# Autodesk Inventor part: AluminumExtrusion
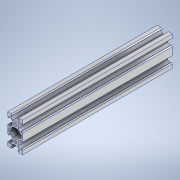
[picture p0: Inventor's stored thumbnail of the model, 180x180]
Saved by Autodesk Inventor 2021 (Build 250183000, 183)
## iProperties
Created: 2026-10
Part Number: AluminumExtrusion
Material: Aluminum 6061
Document SubType Name: Modeling
Designer: hp
Density: 2.7 g/cm^3
Appearance: Aluminum - Flat
Author: hp
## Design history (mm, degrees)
sketch "Sketch1"
  geometry: L1 (-10, -10)-(10, 10); L2 (2.839, -3.9)-(-2.839, -3.9); L3 (-3.9, -2.839)-(-3.9, 2.839); L4 (-2.839, 3.9)-(2.839, 3.9); L5 (3.9, 2.839)-(3.9, -2.839); L6 (3.9, -3.9)-(-3.9, 3.9); L7 (-3.9, -3.9)-(3.9, 3.9); L8 (-5.5, -8.28)-(-5.5, -6.561); L9 (-8.28, -5.5)-(-6.561, -5.5); L10 (-3.9, -2.839)-(-6.561, -5.5); L11 (-2.839, -3.9)-(-5.5, -6.561); L12 (0, -10)-(0, 10); L13 (5.5, -8.28)-(5.5, -6.561); L14 (2.839, -3.9)-(5.5, -6.561); L15 (3.9, -2.839)-(6.561, -5.5); L16 (-3.552, -8.707)-(-4.845, -10); L17 (-3.125, -8.28)-(-0.693, -8.28); L18 (3.552, -8.707)-(4.845, -10); L19 (-5.5, -8.28)-(-3.729, -8.28); L20 (3.729, -8.28)-(5.5, -8.28); L21 (10, -10)-(4.845, -10); L22 (-4.845, -10)-(-10, -10); L23 (-8.707, -3.552)-(-10, -4.845); L24 (-8.28, -5.5)-(-8.28, -3.729); L25 (-10, -4.845)-(-10, -10); L26 (8.707, -3.552)-(10, -4.845); L27 (8.28, -3.729)-(8.28, -5.5); L28 (8.28, -5.5)-(6.561, -5.5); L29 (10, -10)-(10, -4.845); L30 (-5.5, -8.28)-(-3.729, -8.28); L31 (-3.552, -8.707)-(-4.845, -10); L32 (3.125, -8.28)-(0.693, -8.28); L33 (5.5, -8.28)-(3.729, -8.28); L34 (5.5, -8.28)-(3.729, -8.28); L35 (3.9, -2.839)-(6.561, -5.5); L36 (3.9, -3.9)-(-3.9, 3.9); L37 (2.839, -3.9)-(5.5, -6.561); L38 (3.552, -8.707)-(4.845, -10); L39 (3.552, -8.707)-(4.845, -10); L40 (5.5, -8.28)-(5.5, -6.561); L41 (4.845, -10)-(10, -10); L42 (10, -4.845)-(10, -10); L43 (8.28, -5.5)-(6.561, -5.5); L44 (8.28, -5.5)-(8.28, -3.729); L45 (8.707, -3.552)-(10, -4.845); L46 (-10, 0)-(10, 0); L47 (-8.28, 5.5)-(-6.561, 5.5); L48 (-3.9, 2.839)-(-6.561, 5.5); L49 (2.839, 3.9)-(-2.839, 3.9); L50 (2.839, 3.9)-(5.5, 6.561); L51 (3.9, 2.839)-(6.561, 5.5); L52 (8.28, 3.729)-(8.28, 5.5); L53 (8.28, 5.5)-(8.28, 3.729); L54 (8.707, 3.552)-(10, 4.845); L55 (3.9, 2.839)-(6.561, 5.5); L56 (8.28, 5.5)-(6.561, 5.5); L57 (10, 10)-(10, 4.845); L58 (8.28, 5.5)-(6.561, 5.5); L59 (10, 4.845)-(10, 10); L60 (-8.28, 5.5)-(-8.28, 3.729); L61 (-8.707, 3.552)-(-10, 4.845); L62 (-10, 4.845)-(-10, 10); L63 (8.707, 3.552)-(10, 4.845); L64 (-10, -10)-(-10, -4.845)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; C1 r 2.1 at (0, 0); C2 r 2.1 at (0, 20); A1 r 0.25 centre (-8.53, -3.729) between (-8.28, -3.729) and (-8.707, -3.552); A2 r 0.25 centre (-3.729, -8.53) between (-3.552, -8.707) and (-3.729, -8.28); A3 r 0.25 centre (3.729, -8.53) between (3.729, -8.28) and (3.552, -8.707); A4 r 0.25 centre (8.53, -3.729) between (8.707, -3.552) and (8.28, -3.729); A5 r 0.25 centre (8.53, 3.729) between (8.28, 3.729) and (8.707, 3.552); A6 r 0.25 centre (-8.53, 3.729) between (-8.707, 3.552) and (-8.28, 3.729); A7 r 0.25 centre (3.729, 28.53) between (3.552, 28.707) and (3.729, 28.28); A8 r 0.25 centre (-8.53, 23.729) between (-8.707, 23.552) and (-8.28, 23.729); A9 r 0.25 centre (-3.729, 28.53) between (-3.729, 28.28) and (-3.552, 28.707); A10 r 0.25 centre (-8.53, 16.271) between (-8.28, 16.271) and (-8.707, 16.448); A11 r 0.25 centre (8.53, 16.271) between (8.707, 16.448) and (8.28, 16.271); A12 r 0.25 centre (8.53, 23.729) between (8.28, 23.729) and (8.707, 23.552); 2 further points
  constraints: 300 end point, 43 symmetric about line, 24 point on circle, 14 centre point, 8 parallel, 8 point on line, 7 perpendicular, 6 midpoint, 3 horizontal, 2 coincident, 2 tangent, 1 vertical, 5 other
  dimensions: "d0" = 4.2 diameter of C1; "d2" = 20 distance of L1.start L62.end; "d9" = 1.5 distance between parallel lines of L11 L10; "d12" = 6.25 distance of L17.start L32.start; "d14" = 45 deg angle of L16 L19; "d19" = 0.5 diameter of A1
extrude "Extrusion1" new body sketch "Sketch1" distance "d20" = 200; taper "d21" = 0 deg
body "Solid1"
other parameters: "d5" = 6.1, "d10" = 4.5
